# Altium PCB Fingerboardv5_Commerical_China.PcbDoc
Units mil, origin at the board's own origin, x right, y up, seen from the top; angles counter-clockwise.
Board outline 600 x 1050 mil, 2 copper layers (Top Layer, Bottom Layer); 12 components, 14 nets, 70 pads, 13 vias.
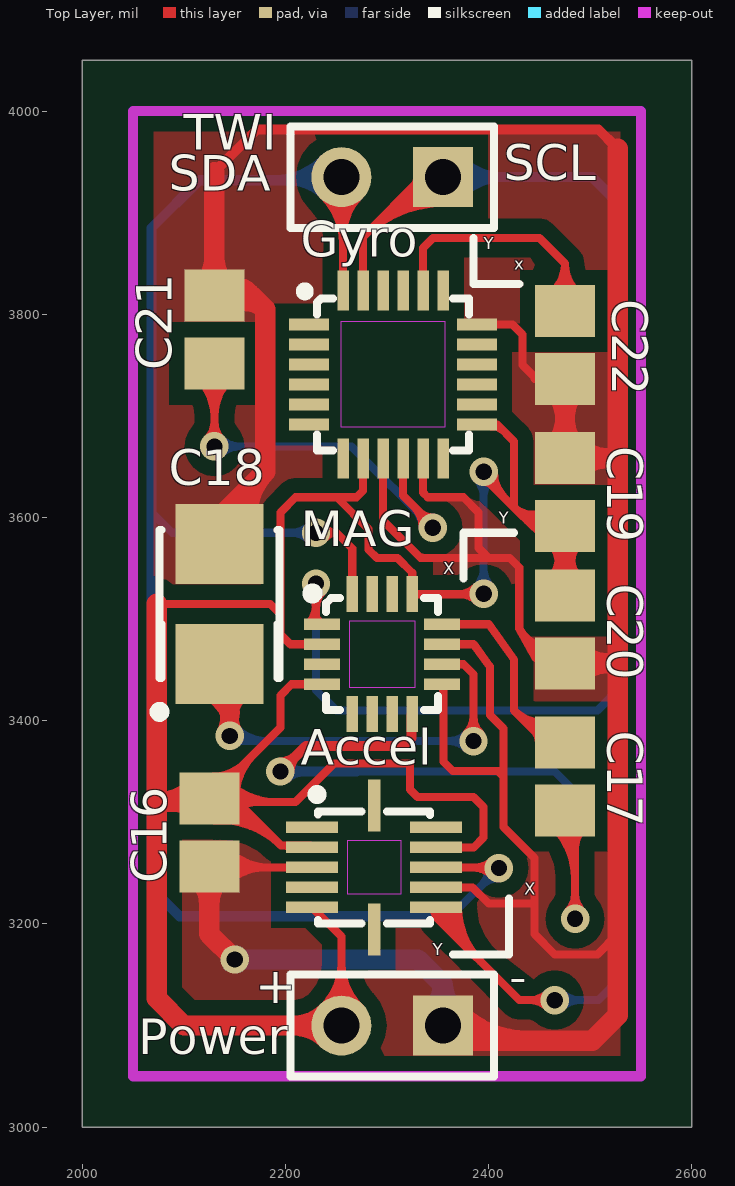
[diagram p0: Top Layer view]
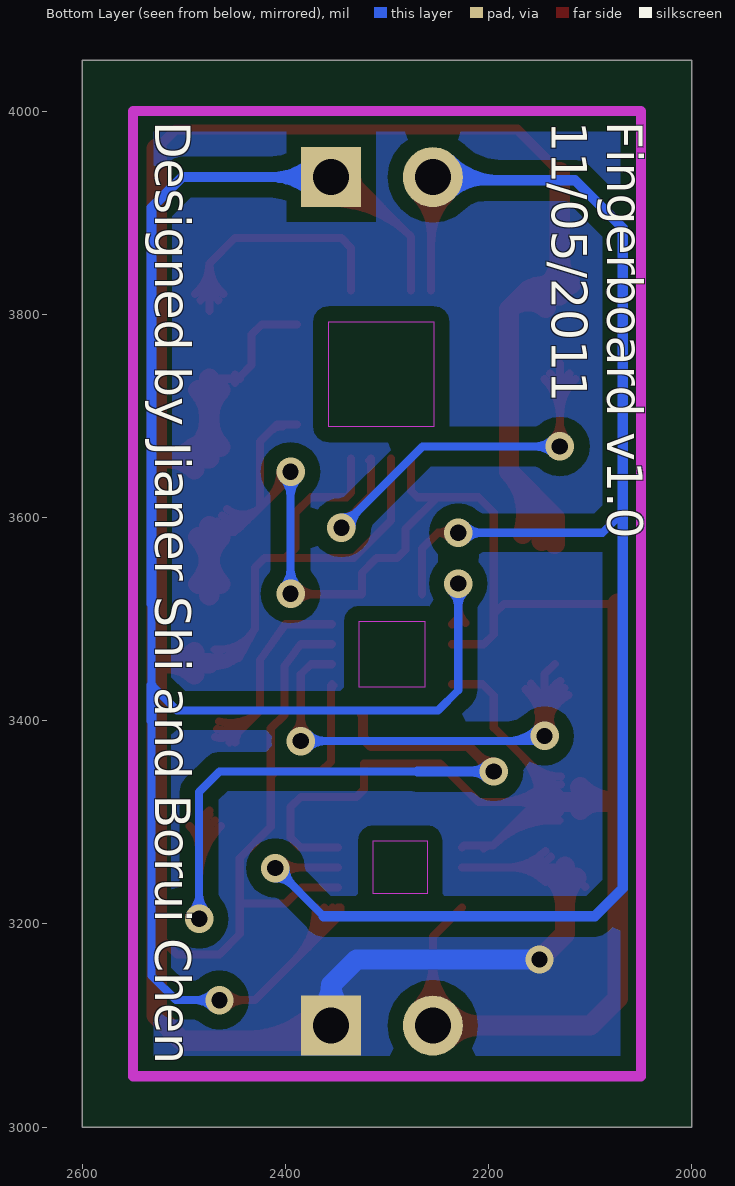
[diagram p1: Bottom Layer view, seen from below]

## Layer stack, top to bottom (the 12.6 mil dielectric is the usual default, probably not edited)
Top Layer: signal copper 1.4
Dielectric: dielectric 12.6, FR-4, Dk 4.8
Bottom Layer: signal copper 1.4

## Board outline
2000,3000 2600,3000 2600,4050 2000,4050

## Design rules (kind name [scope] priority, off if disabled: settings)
Clearance "Polygon Clearance" [InPolygon] p1: gap=15
Clearance [All] p2: gap=8.1
HoleSize [All] p1: absolutevalues=TRUE maxlimit=100 minlimit=16 maxpercent=80.000 minpercent=20.000
MinimumAnnularRing [All] p1: minimumring=6
PolygonConnect [All] p1: connectstyle=Direct reliefconductorwidth=10 reliefentries=4 polygonreliefangle="90 Angle"
RoutingVias [All] p1: holewidth=16 width=28 viastyle="Through Hole" minholewidth=16 minwidth=27 maxholewidth=16 maxwidth=35
SilkscreenOverComponentPads [All] p1: minsilkscreentomaskgap=10
SolderMaskExpansion [All] p1: expansion=4
Width [All] p1: maxlimit=50 minlimit=8 preferedwidth=8
26 further rules are at their usual default settings.

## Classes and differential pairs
net class TWI[1..0]: TWI0 TWI1
net class AUX_TWI[1..0]: AUX_TWI0 AUX_TWI1
component class U_IMU3000: C19 C20 C21 C22 Gyro
component class U_HMC5883L: C17 C18 MAG
component class U_BMA180: Accel C16
component class Fingerboard: Power TWI

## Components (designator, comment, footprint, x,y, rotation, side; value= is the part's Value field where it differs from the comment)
Accel "BMA180" "BMA180 - ECESHOP" 2240,3295 r270 top
C16 "Cap Semi" CAPC2012N 2125,3290 r90 top
C17 "Cap Semi" CAPC2012N 2475,3345 r90 top
C18 "Cap Pol1" TC3528-1411 2135,3515 r90 top
C19 "Cap Semi" CAPC2012N 2475,3625 r270 top
C20 "Cap Semi" CAPC2012N 2475,3490 r90 top
C21 "Cap Semi" CAPC2012N 2130,3785 r270 top
C22 "Cap Semi" CAPC2012N 2475,3770 r90 top
Gyro "IMU3000" "IMU3000 - ECESHOP" 2235,3790 r0 top
MAG "HMC5883L" "HMC5883L - ECESHOP" 2245,3495 r0 top
Power "Header 2" HDR1X2 2355,3100 r180 top
TWI "TWI" HDR1X2 2355,3935 r180 top

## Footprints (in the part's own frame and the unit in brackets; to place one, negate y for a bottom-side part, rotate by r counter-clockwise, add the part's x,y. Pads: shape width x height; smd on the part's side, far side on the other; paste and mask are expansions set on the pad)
"BMA180 - ECESHOP" [mm] "BMA180 - ECESHOP"
  rect 0.29x1.3 smd: 1(0,-0.35) 2(0.5,-0.35) 3(1,-0.35) 4(1.5,-0.35) 5(2,-0.35) 7(2,2.75) 8(1.5,2.75) 9(1,2.75) 10(0.5,2.75) 11(0,2.75)
  rect 1.3x0.32 smd: 6(2.55,1.2) 12(-0.55,1.2)
  Keep-Out Layer region: 0.328,0.524 1.658,0.524 1.658,1.876 0.328,1.876
  silkscreen extent -0.91,-0.31 2.4,2.6
CAPC2012N [mm] "Chip Capacitor, Body 2.0x1.3mm, IPC Medium Density"
  rect 1.3x1.5 smd: 1(-0.85,0) 2(0.85,0)
  body extent -1.1,-0.72 1.1,0.72, height 1.1
HDR1X2 [mm] "Connector; Header; 2 Position"
  rect 1.5x1.5 hole 0.9: 1(0,0)
  round 1.5 hole 0.9: 2(2.54,0)
  silkscreen extent -1.27,-1.27 3.81,1.27
"HMC5883L - ECESHOP" [mm]
  rect 0.9x0.29 smd: 1(-0.225,0) 2(-0.225,-0.5) 3(-0.225,-1) 4(-0.225,-1.5) 9(2.775,-1.5) 10(2.775,-1) 11(2.775,-0.5) 12(2.775,0)
  rect 0.29x0.9 smd: 5(0.525,-2.25) 6(1.025,-2.25) 7(1.525,-2.25) 8(2.025,-2.25) 13(2.025,0.75) 14(1.525,0.75) 15(1.025,0.75) 16(0.525,0.75)
  Keep-Out Layer region: 0.452,-1.572 2.099,-1.572 2.099,0.075 0.452,0.075
  silkscreen extent -0.57,-2.15 2.67,0.87
"IMU3000 - ECESHOP" [mm]
  rect 1x0.29 smd: 1(-0.3,0) 2(-0.3,-0.5) 3(-0.3,-1) 4(-0.3,-1.5) 5(-0.3,-2) 6(-0.3,-2.5) 13(3.9,-2.5) 14(3.9,-2) 15(3.9,-1.5) 16(3.9,-1) 17(3.9,-0.5) 18(3.9,0)
  rect 0.29x1 smd: 7(0.55,-3.35) 8(1.05,-3.35) 9(1.55,-3.35) 10(2.05,-3.35) 11(2.55,-3.35) 12(3.05,-3.35) 19(3.05,0.85) 20(2.55,0.85) 21(2.05,0.85) 22(1.55,0.85) 23(1.05,0.85) 24(0.55,0.85)
  Keep-Out Layer region: 0.488,-2.562 3.109,-2.562 3.109,0.066 0.488,0.066
  silkscreen extent -0.48,-3.15 3.7,0.9
TC3528-1411 [mm] "Capacitor, SM Tantalum; Body 3.5 x 2.8 mm (LxW typ)"
  rect 2x2.2 smd: 1(-1.5,0) 2(1.5,0)
  silkscreen extent -2.82,-1.5 1.85,1.62

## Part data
C16 C17 C19 C20 C21 C22: "Capacitor (Semiconductor SIM Model)"
C18: "Polarized Capacitor (Radial)"
Power: "Header, 2-Pin"
TWI: library part "Header 2", "Header, 2-Pin"

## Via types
v1: diameter 28, hole 16, Top Layer to Bottom Layer, 13 vias

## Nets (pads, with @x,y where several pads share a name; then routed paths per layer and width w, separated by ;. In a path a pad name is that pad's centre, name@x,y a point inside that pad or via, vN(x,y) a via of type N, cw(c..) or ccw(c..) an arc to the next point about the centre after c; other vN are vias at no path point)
3.3VCC: Accel.2 Accel.5 Accel.10 C16.2 C19.2 C20.2 Gyro.8 Gyro.13 MAG.2 MAG.4 MAG.13 Power.2 | length 3692.5
  Top Layer w8: 2073.1,3515 2185,3515 2195,3505 ; C16.2 C16.2@2125.33,3323.46 ; C16.2@2128.79,3325.87 cw(c2131.14,3287.97) 2157.99,3314.82 ; C16.2@2128.94,3337.06 ccw(c2128.94,3361.15) C16.2@2145.97,3344.11 ; C16.2@2128.94,3345.06 ccw(c2128.94,3388.46) 2159.63,3357.77 ; C16.2@2129.28,3317.88 cw(c2132.61,3264.36) 2170.53,3302.28 ; C16.2@2129.78,3309.9 cw(c2134.07,3240.74) 2183.07,3289.74 ; C16.2@2130.27,3301.92 cw(c2135.54,3217.12) 2195.62,3277.19 ; C16.2@2131.54,3320 C16.2@2152.81,3320 ; C16.2@2138.55,3333.07 ccw(c2170.11,3364.64) 2170.11,3320 ; C16.2@2142.53,3323.46 cw(c2184.06,3323.46) 2154.69,3352.83 ; C16.2@2144.2,3308.2 cw(c2172.7,3279.7) 2172.7,3320 ; C16.2@2144.2,3338.73 ccw(c2189.43,3383.95) 2189.43,3320 ; C16.2@2150.53,3323.46 cw(c2211.37,3323.46) 2168.35,3366.49 ; 2195,3320 2210,3320 2247.9,3357.9 2322.66,3357.9 2322.66,3332.34 2330,3325 2385,3325 2395,3315 2395,3285 2385.32,3275.32 Accel.10 ; 2197.68,3277.19 cw(c2197.68,3266.66) Accel.2@2205.13,3274.11 ; 2205,3320 C16.2@2152.81,3320 ; Accel.5 2255,3187.48 Power.2 ; Accel.2 2224.34,3277.19 2195.62,3277.19 ; MAG.4 2205.95,3435.95 2195,3425 2195,3393.14 C16.2@2125.33,3323.46 ; MAG.2 2205.32,3475.32 2205,3475 2195,3485 2195,3505 ; Power.2@2236.95,3118.05 ccw(c2193.37,3161.63) 2255,3161.63 ccw(c2316.63,3161.63) Power.2@2273.05,3118.05 ; Power.2@2242.61,3112.39 ccw(c2212.68,3142.32) 2255,3142.32 ccw(c2297.32,3142.32) Power.2@2267.39,3112.39 ; Gyro.8 2276.34,3626.34 2270,3620 2250.37,3620 ; 2369.72,3524.53 ccw(c2369.72,3550.28) v1@2387.93,3532.07 ; 2372,3524.53 cw(c2372,3502) v1@2387.93,3517.93 ; Gyro.13 2408.43,3691.57 2425,3675 2425,3610 ; v1(2395,3525) 2394.53,3524.53 MAG.13 2324.72,3545.65 2310.37,3560 2290,3560 2281.77,3568.23 2281.77,3588.6 2250.37,3620 ; v1@2395,3635 cw(c2395,3622.93) 2403.54,3631.46 ; v1(2395,3645) 2395,3640 2425,3610 ; Gyro.13@2402.52,3689.87 cw(c2402.52,3671.48) 2415.52,3684.48 ; v1@2405,3645 ccw(c2441.21,3645) 2415.61,3619.39 ; 2431.28,3603.72 ccw(c2447.8,3620.24) C19.2@2462.5,3602.09 ; 2437.56,3597.44 ccw(c2453.42,3613.3) C19.2@2467.54,3595.88 ; 2443.84,3591.16 ccw(c2459.04,3606.36) C19.2@2472.58,3589.66 ; C19.2@2449.63,3594.1 cw(c2445,3594.66) 2445,3590 ; C19.2@2450.19,3586 ccw(c2445,3584.63) 2445,3590 ; C19.2@2457.47,3608.31 cw(c2442.17,3627.17) 2425,3610 ; C19.2 2473.46,3590 2445,3590 ; C16.2@2125.33,3323.46 2149.34,3323.46 C16.2@2152.81,3320 ; C16.2@2152.81,3320 2195.62,3277.19 ; 2195,3505 2195,3605 2210,3620 2250.37,3620 ; 2425,3610 2445,3590
  Top Layer w20: 2073.1,3515 2073.1,3320 ; 2075.06,3320 ccw(c2075.06,3369.47) C16.2@2110.04,3334.49 ; 2091.79,3320 cw(c2091.79,3294.19) C16.2@2110.04,3312.44 ; C16.2@2131.54,3320 2073.1,3320 ; Power.2@2241.19,3086.19 ccw(c2207.86,3052.86) 2207.86,3100 ccw(c2207.86,3147.14) Power.2@2241.19,3113.81 ; Power.2 2100,3100 2073.1,3126.9 2073.1,3320 ; C20.2@2463.98,3534.49 ccw(c2437.36,3561.1) 2475,3561.1 ccw(c2512.64,3561.1) C20.2@2486.02,3534.49 ; C19.2@2463.98,3580.51 cw(c2437.36,3553.9) 2475,3553.9 cw(c2512.64,3553.9) C19.2@2486.02,3580.51 ; C20.2 C19.2
  Bottom Layer w8: v1@2387.93,3532.07 ccw(c2370.86,3549.14) 2395,3549.14 ccw(c2419.14,3549.14) v1@2402.07,3532.07 ; v1@2387.93,3637.93 cw(c2370.86,3620.86) 2395,3620.86 cw(c2419.14,3620.86) v1@2402.07,3637.93 ; v1(2395,3525) v1@2400,3530 ; v1@2395,3535 v1(2395,3645) v1@2400,3640
AUX_TWI0: Gyro.7
AUX_TWI1: Gyro.6
GND: Accel.3 Accel.8 C16.1 C18.2 C19.1 C20.1 C21.1 C22.1 Gyro.9 Gyro.11 Gyro.18 MAG.9 MAG.11 Power.1 | length 4902.2
  Top Layer w8: C16.1@2105,3236.54 C16.1 2125.91,3255.63 Accel.3 ; C16.1@2138.55,3246.93 cw(c2159.56,3225.91) 2159.56,3255.63 ; C16.1@2138.55,3266.15 ccw(c2163.93,3291.53) 2163.93,3255.63 ; C16.1@2144.2,3241.27 cw(c2178.88,3206.6) 2178.88,3255.63 ; C16.1@2144.2,3271.8 ccw(c2183.25,3310.85) 2183.25,3255.63 ; Gyro.9 2296.02,3597.12 2332.74,3560.4 2334.6,3560.4 2335,3560 2400,3560 ; Gyro.11 2335.39,3624.61 2340,3620 2375,3620 2390,3605 2390,3570 2400,3560 ; Accel.8 2384.05,3235.95 2400,3220 2445,3220 ; MAG.9@2353.04,3434.74 cw(c2347.36,3429.05) 2355.4,3429.05 ; MAG.9 2355.4,3434.8 2355.4,3359.6 2364.6,3350.4 2409.2,3350.4 2414.6,3345 ; MAG.11 2385,3475.32 2401.1,3453.36 2401.1,3405.76 2414.6,3392.26 2414.6,3345 ; Gyro.18 2423.37,3790 2433.37,3780 2433.37,3750 2445,3738.37 2445,3736.63 ; 2430.02,3490.77 ccw(c2465.54,3510.45) C20.1@2469.68,3470.06 ; 2435.89,3480.17 ccw(c2466.88,3497.34) C20.1@2470.49,3462.1 ; 2441.76,3469.57 ccw(c2468.23,3484.23) C20.1@2471.31,3454.14 ; C22.1@2449.83,3732.61 ccw(c2445,3731.71) 2445,3736.63 ; C22.1@2449.87,3740.64 cw(c2445,3741.58) 2445,3736.63 ; C20.1@2470.59,3460.95 C20.1 2446.1,3461.75 2430,3490.81 2430,3550.69 2420.69,3560 2400,3560 ; C22.1 2474.91,3736.63 2445,3736.63 ; 2526.9,3190 2506.9,3170 2465,3170 2445,3190 2445,3220 ; 2414.6,3345 2414.6,3295.4 2445,3265 2445,3220
  Top Layer w10: 2130,3940 2171.9,3981.9 2508.1,3981.9 2525,3965
  Top Layer w20: C16.1@2113.98,3245.51 cw(c2087.36,3218.9) 2125,3218.9 cw(c2162.64,3218.9) C16.1@2136.02,3245.51 ; C21.1@2118.98,3829.49 ccw(c2092.36,3856.1) 2130,3856.1 ccw(c2167.64,3856.1) C21.1@2141.02,3829.49 ; C16.1 2125,3190 v1(2150,3165) ; 2130,3940 C21.1 2166.54,3818.46 ; C21.1@2131.1,3821.84 cw(c2147.07,3802.88) 2164.59,3820.41 ; C18.2 2135,3600 2180,3645 ; C21.1@2143.98,3806.54 cw(c2161.15,3786.15) 2180,3805 ; C21.1@2146.07,3808.68 cw(c2166.53,3792.18) 2166.53,3818.46 ; C21.1@2146.07,3828.25 ccw(c2166.53,3844.75) 2166.53,3818.46 ; C18.2@2147.74,3577.27 cw(c2188.5,3592.14) 2157.82,3622.82 ; C18.2@2166.53,3584.12 cw(c2221,3604) 2180,3645 ; Power.1@2354.67,3099.67 ccw(c2390.07,3135.07) 2390.07,3085 ; Power.1 2370,3085 2501.9,3085 2526.9,3110 2526.9,3190 2526.9,3460 ; Power.1@2368.81,3113.81 ccw(c2438.36,3183.36) 2438.36,3085 ; C19.1@2463.98,3669.49 ccw(c2437.36,3696.1) 2475,3696.1 ccw(c2512.64,3696.1) C19.1@2486.02,3669.49 ; C22.1@2463.98,3725.51 cw(c2437.36,3698.9) 2475,3698.9 cw(c2512.64,3698.9) C22.1@2486.02,3725.51 ; C20.1 2523.44,3456.54 2526.9,3460 ; C22.1 C19.1 2523.44,3658.46 2526.9,3655 ; C20.1@2489.96,3445.51 cw(c2516.58,3418.9) 2516.58,3456.54 cw(c2516.58,3494.17) C20.1@2489.96,3467.56 ; C19.1@2489.96,3647.44 cw(c2516.58,3620.83) 2516.58,3658.46 cw(c2516.58,3696.1) C19.1@2489.96,3669.49 ; 2526.9,3963.1 2526.9,3655 ; 2166.54,3818.46 2180,3805 ; 2180,3645 2180,3805 ; 2526.9,3460 2526.9,3655
  Bottom Layer w20: v1(2150,3165) 2330,3165 2355,3140 ; Power.1@2342.99,3115.4 ccw(c2323.8,3140) 2355,3140 ; Power.1 2355,3140 ; Power.1@2367.01,3115.4 cw(c2386.2,3140) 2355,3140
NetAccel_4: Accel.4
NetC17_1: C17.1 MAG.8 | length 995
  Top Layer w8: C17.1@2463.67,3296.27 cw(c2412.18,3244.77) 2485,3244.77 ; C17.1@2469.33,3301.93 cw(c2431.49,3264.09) 2485,3264.09 ; C17.1@2474.98,3307.58 cw(c2450.8,3283.4) 2485,3283.4 ; C17.1 2485,3301.54 v1(2485,3205) ; v1@2477.93,3212.07 ccw(c2460.86,3229.14) 2485,3229.14 ccw(c2509.14,3229.14) v1@2492.07,3212.07 ; 2485,3274.05 cw(c2516.42,3274.05) C17.1@2494.2,3296.27
  Top Layer w10: v1(2195,3350) 2220,3375 2315.57,3375 2323.85,3383.27 2323.85,3405.54 MAG.8 ; v1@2195,3359 ccw(c2195,3380.73) 2210.36,3365.36 ccw(c2225.73,3350) v1@2204,3350
  Bottom Layer w8: 2270,3350 2465,3350 2485,3330 v1(2485,3205) ; v1@2477.93,3212.07 ccw(c2460.86,3229.14) 2485,3229.14 ccw(c2509.14,3229.14) v1@2492.07,3212.07
  Bottom Layer w10: v1(2195,3350) 2270,3350 ; v1@2201.36,3343.64 cw(c2216.73,3328.27) 2216.73,3350 cw(c2216.73,3371.73) v1@2201.36,3356.36
NetC17_2: C17.2 MAG.12 | length 302.6
  Top Layer w8: MAG.12 2400,3495 2425,3460 2425,3410 ; 2434.74,3400.26 ccw(c2458.59,3424.1) C17.2@2467.48,3391.57 ; C17.2@2449.47,3378.46 ccw(c2432.42,3378.46) 2444.48,3390.52 ccw(c2462.77,3408.8) C17.2@2469.59,3383.86 ; C17.2@2455,3378.46 2455,3380 2425,3410 ; C17.2@2465.37,3399.29 cw(c2454.4,3439.4) 2425,3410
NetC18_1: C18.1 MAG.10 | length 897
  Top Layer w8: C18.1@2121.46,3425.19 cw(c2098.48,3384.74) v1@2145,3384.74 ; C18.1@2125.41,3432.15 cw(c2106.29,3398.49) v1@2145,3398.49 ; C18.1@2129.37,3439.1 cw(c2114.1,3412.24) 2145,3412.24 ; C18.1 2145,3445.94 v1(2145,3385) ; v1@2136.34,3390.01 ccw(c2115.71,3401.95) 2138.74,3408.12 ccw(c2161.46,3414.2) v1@2149.91,3393.71 ; v1@2137.13,3391.17 ccw(c2118.39,3405.84) 2141.38,3412 ; v1@2137.93,3392.07 ccw(c2120.86,3409.14) 2145,3409.14 ccw(c2169.14,3409.14) v1@2152.07,3392.07 ; v1@2140,3393.66 ccw(c2128.01,3414.42) 2151.17,3408.22 ; 2144.31,3401.08 ccw(c2156.11,3404.24) v1@2150,3393.66 ; v1@2145,3385.19 cw(c2209.69,3385.19) C18.1@2163.95,3430.93 ; 2145,3404.51 cw(c2190.38,3404.51) C18.1@2158.29,3436.59 ; 2151.23,3408.45 ccw(c2174.71,3402.16) v1@2153.66,3390 ; MAG.10 2375.1,3455.63 2385,3445.73 v1(2385,3380) ; v1@2377.93,3387.07 ccw(c2360.86,3404.14) 2385,3404.14 ccw(c2409.14,3404.14) v1@2392.07,3387.07
  Bottom Layer w8: v1(2145,3385) 2150,3380 v1(2385,3380) ; v1@2146.41,3386.41 ccw(c2161.9,3401.9) 2161.9,3380 ; v1@2152.07,3392.07 ccw(c2181.21,3421.21) 2181.21,3380 ; v1@2377.93,3372.93 ccw(c2360.86,3355.86) 2360.86,3380 ccw(c2360.86,3404.14) v1@2377.93,3387.07
NetC21_2: C21.2 Gyro.10 | length 697.7
  Top Layer w8: C21.2@2114.73,3736.27 cw(c2077.88,3699.41) 2130,3699.41 cw(c2182.12,3699.41) C21.2@2145.27,3736.27 ; C21.2@2120.39,3741.93 cw(c2097.19,3718.72) 2130,3718.72 cw(c2162.81,3718.72) C21.2@2139.61,3741.93 ; v1@2122.93,3677.07 ccw(c2105.86,3694.14) 2130,3694.14 ccw(c2154.14,3694.14) v1@2137.07,3677.07 ; v1(2130,3670) C21.2 ; Gyro.10@2317.58,3656.23 Gyro.10 2315.71,3621.52 2345,3592.23 v1(2345,3590) ; 2326.35,3610.88 cw(c2305.47,3590) v1@2335,3590 ; 2331.74,3605.49 ccw(c2345,3618.76) v1@2345,3600
  Bottom Layer w8: v1(2130,3670) 2265,3670 v1(2345,3590) ; v1@2137.07,3662.93 cw(c2154.14,3645.86) 2154.14,3670 cw(c2154.14,3694.14) v1@2137.07,3677.07 ; v1@2335,3590 ccw(c2310.86,3590) 2327.93,3607.07 ccw(c2345,3624.14) v1@2345,3600
NetC22_2: C22.2 Gyro.20 | length 353.8
  Top Layer w8: Gyro.20 2335.39,3865.39 2345,3875 2450,3875 2475,3850 ; C22.2@2461.06,3819.95 ccw(c2435.65,3850) 2475,3850 ; C22.2@2466.22,3813.84 ccw(c2450.23,3832.76) 2475,3832.76 ccw(c2499.77,3832.76) C22.2@2483.78,3813.84 ; C22.2 2475,3850 ; C22.2@2488.94,3819.95 cw(c2514.35,3850) 2475,3850
NetGyro_12: Gyro.12
NetINT_3: MAG.15
TWI0: Accel.7 Gyro.23 MAG.1 TWI.1 | length 2534.7
  Top Layer w8: MAG.1@2222.93,3496.21 ccw(c2205.85,3513.29) 2230,3513.29 ; v1@2222.93,3527.93 cw(c2205.86,3510.86) 2230,3510.86 cw(c2254.14,3510.86) v1@2237.07,3527.93 ; v1(2230,3535) 2230,3501.14 MAG.1 ; Gyro.23 2276.34,3876.34 2335,3935 TWI.1 ; 2277.28,3877.28 cw(c2355,3799.56) TWI.1@2355,3909.47 ; 2290.94,3890.94 cw(c2355,3826.87) TWI.1@2355,3917.47 ; 2304.59,3904.59 cw(c2355,3854.19) TWI.1@2355,3925.47 ; 2318.25,3918.25 cw(c2355,3881.5) TWI.1@2355,3933.47 ; TWI.1@2325.56,3925.56 ccw(c2316.13,3935) TWI.1@2329.47,3935 ; Accel.7@2345.86,3216.26 ccw(c2363.04,3216.26) 2350.89,3204.11 ; Accel.7 2348.27,3206.73 2430,3125 v1(2465,3125) ; Accel.7@2353.86,3216.26 ccw(c2390.36,3216.26) 2364.55,3190.45 ; Accel.7@2361.86,3216.26 ccw(c2417.67,3216.26) 2378.21,3176.79 ; Accel.7@2369.86,3216.26 ccw(c2444.98,3216.26) 2391.86,3163.14 ; v1@2457.93,3117.93 ccw(c2440.86,3100.86) 2440.86,3125 ccw(c2440.86,3149.14) v1@2457.93,3132.07
  Bottom Layer w8: v1@2222.93,3527.93 cw(c2205.86,3510.86) 2230,3510.86 cw(c2254.14,3510.86) v1@2237.07,3527.93 ; v1(2230,3535) 2230,3430 2250,3410 2506.9,3410 2531.9,3435 2531.9,3515 ; v1(2465,3125) 2507.9,3125 2531.9,3149 2531.9,3400 ; v1@2472.07,3117.93 cw(c2489.14,3100.86) 2489.14,3125 cw(c2489.14,3149.14) v1@2472.07,3132.07
  Bottom Layer w10: TWI.1 2501.9,3935 2531.9,3905 2531.9,3515 ; TWI.1@2365.27,3924.73 cw(c2390.07,3899.93) 2390.07,3935 cw(c2390.07,3970.07) TWI.1@2365.27,3945.27 ; TWI.1@2372.34,3917.66 cw(c2414.21,3875.79) 2414.21,3935 cw(c2414.21,3994.21) TWI.1@2372.34,3952.34 ; 2531.9,3400 2531.9,3435
TWI1: Accel.9 Gyro.24 MAG.16 TWI.2 | length 2103.6
  Top Layer w8: v1(2230,3585) 2250,3585 ; TWI.2@2236.95,3916.95 cw(c2189.38,3869.38) 2256.65,3869.38 ; v1@2238,3579 cw(c2250,3570) 2250,3585 ; v1@2238,3591 ccw(c2250,3600) 2250,3585 ; TWI.2@2242.61,3922.61 cw(c2208.69,3888.69) 2256.65,3888.69 ; TWI.2 2256.65,3933.35 Gyro.24 ; 2256.65,3877.36 cw(c2312.64,3877.36) TWI.2@2273.05,3916.95 ; 2256.65,3896.68 cw(c2293.32,3896.68) TWI.2@2267.39,3922.61 ; MAG.16 2265.67,3569.33 2250,3585 ; Accel.9 2409.37,3255.63 v1(2410,3255) v1@2404.37,3260.63 ; 2384.34,3255.63 cw(c2384.34,3229.34) v1@2402.93,3247.93 ; 2387.38,3255.63 ccw(c2387.38,3277.62) v1@2402.93,3262.07
  Bottom Layer w8: 2068.1,3605 2088.1,3585 v1(2230,3585) ; v1@2222.93,3577.93 ccw(c2205.86,3560.86) 2205.86,3585 ccw(c2205.86,3609.14) v1@2222.93,3592.07 ; 2362.5,3207.5 v1(2410,3255) ; v1@2400,3255 cw(c2375.86,3255) 2392.93,3237.93 cw(c2410,3220.86) v1@2410,3245
  Bottom Layer w10: 2188.3,3931.9 ccw(c2188.3,4001.7) TWI.2@2237.66,3952.34 ; 2203.27,3931.9 cw(c2203.27,3883.27) TWI.2@2237.66,3917.66 ; 2212.44,3931.9 ccw(c2212.44,3977.56) TWI.2@2244.73,3945.27 ; TWI.2 2251.9,3931.9 2115,3931.9 2068.1,3885 2068.1,3605 2068.1,3235 2095.6,3207.5 2362.5,3207.5
pads on no net: Accel.1 Accel.6 Accel.11 Accel.12 Gyro.1 Gyro.2 Gyro.3 Gyro.4 Gyro.5 Gyro.14 Gyro.15 Gyro.16 Gyro.17 Gyro.19 Gyro.21 Gyro.22 MAG.3 MAG.5 MAG.6 MAG.7 MAG.14

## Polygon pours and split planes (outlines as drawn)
GND on Bottom Layer "Bottom Layer-GND" (solid, pour order 4): 2025,4025 2575,4025 2575,3025 2025,3025
GND on Top Layer "Top Layer-GND" (solid, pour order 2): 2025,4025 2575,4025 2575,3025 2025,3025

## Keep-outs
Keep-Out Layer:
  lines w10: 2050,3050 2050,4000 2550,4000 2550,3050 2050,3050

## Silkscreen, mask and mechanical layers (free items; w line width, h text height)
Top Overlay:
  lines w8: 2365,3170 2420,3170 2420,3225 ; 2375,3540 2375,3585 2425,3585 ; 2385,3875 2385,3830 2430,3830
  text "SCL" at 2415,3920 h60
  text "SDA" at 2085,3910 h60
  text "Y" at 2395,3860 h20
  text "x" at 2425,3840 h20
  text "Y" at 2410,3590 h20
  text "X" at 2355,3540 h20
  text "X" at 2435,3225 h20
  text "Y" at 2345,3165 h20
  text "-" at 2420,3120 h60
  text "+" at 2170,3110 h60
Bottom Overlay:
  text "Fingerboard v1.0" at 2095,3990 h60 r90
  text "11/05/2011" at 2150,3990 h60 r90
  text "Designed by Jianer Shi and Borui Chen" at 2540,3990 h60 r90

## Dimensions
2050,3050 to 2050,4000 on Mechanical 1
2050,3050 to 2550,3050 on Mechanical 1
